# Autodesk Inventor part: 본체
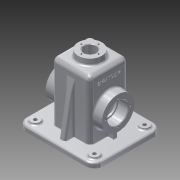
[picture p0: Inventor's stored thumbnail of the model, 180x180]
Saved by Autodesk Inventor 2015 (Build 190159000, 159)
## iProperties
Created: 2016-02
Part Number: 본체
Material: 알루미늄 6061
Document SubType Name: Modeling
Designer: Administrator
Density: 2.7 g/cm^3
Appearance: 알루미늄 - 평지
Mass: 856.212 g
Surface Area: 918.664 cm^2
Volume: 317.116 cm^3
Author: Administrator
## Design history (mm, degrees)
sketch "스케치1"
  geometry: L1 (-65, -57.5)-(65, -57.5); L2 (65, -57.5)-(65, 57.5); L3 (65, 57.5)-(-65, 57.5); L4 (-65, 57.5)-(-65, -57.5); L5 (-65, -57.5)-(65, 57.5); L6 (65, -57.5)-(-65, 57.5); 1 further point
  constraints: 12 end point, 2 midpoint, 2 parallel, 1 horizontal, 1 perpendicular
  dimensions: "d0" = 130 distance of L2.end L3.end; "d1" = 115 distance of L1.end L2.end
extrude "돌출1" new body sketch "스케치1" distance "d2" = 8; taper "d3" = 0 deg
sketch "스케치2"
  geometry: L1 (-60, -52.5)-(60, -52.5); L2 (60, -52.5)-(60, 52.5); L3 (60, 52.5)-(-60, 52.5); L4 (-60, 52.5)-(-60, -52.5); L5 (-60, -52.5)-(60, 52.5); L6 (60, -52.5)-(-60, 52.5); 1 further point
  constraints: 12 end point, 2 midpoint, 2 parallel, 1 horizontal, 1 perpendicular
  dimensions: "d4" = 120 distance of L2.end L3.end; "d5" = 105 distance of L1.end L2.end
extrude "돌출2" join sketch "스케치2" distance "d6" = 2; taper "d7" = 0 deg
sketch "스케치4"
  geometry: L1 (-65, -57.5)-(-65, 57.5) reference; L2 (-65, 57.5)-(65, 57.5) reference; L3 (65, 57.5)-(65, -57.5) reference; L4 (65, -57.5)-(-65, -57.5) reference; L5 (-32.5, -32.5)-(32.5, -32.5); L6 (32.5, -32.5)-(32.5, 32.5); L7 (32.5, 32.5)-(-32.5, 32.5); L8 (-32.5, 32.5)-(-32.5, -32.5); L9 (-32.5, -32.5)-(32.5, 32.5); L10 (32.5, -32.5)-(-32.5, 32.5); L11 (-5, 32.5)-(-5, 47.5); L12 (-5, 47.5)-(5, 47.5); L13 (5, 47.5)-(5, 32.5); L14 (-5, -32.5)-(-5, -47.5); L15 (-5, -47.5)-(5, -47.5); L16 (5, -47.5)-(5, -32.5); L17 (32.5, 3)-(42.5, 3); L18 (42.5, 3)-(42.5, -3); L19 (42.5, -3)-(32.5, -3); L20 (-32.5, 3)-(-42.5, 3); L21 (-42.5, 3)-(-42.5, -3); L22 (-42.5, -3)-(-32.5, -3); 8 further points
  constraints: 36 end point, 9 midpoint, 8 perpendicular, 8 point on line, 4 horizontal, 2 horizontal alignment, 2 parallel, 2 vertical, 2 vertical alignment
  dimensions: "d8" = 65 distance of L6.end L7.end; "d9" = 65 distance of L5.end L6.end; "d10" = 15 distance between parallel lines of L7 L12; "d11" = 10 distance of L11.end L12.end; "d12" = 15 distance between parallel lines of L15 L5; "d13" = 10 distance of L14.end L15.end; "d14" = 10 distance between parallel lines of L6 L18; "d15" = 6 distance of L17.end L18.end; "d16" = 6 distance of L20.end L21.end; "d17" = 10 distance between parallel lines of L21 L8
  node "절단 모서리 투영1"
extrude "돌출3" join sketch "스케치4" distance "d18" = 67.5; taper "d19" = 0 deg
extrude "돌출4" join sketch "스케치4" distance "d20" = 60; taper "d21" = 0 deg
sketch "스케치5"
  geometry: L1 (-75.5, -20)-(-77.5, -20) reference; L2 (-77.5, -20)-(-77.5, 85) reference; L3 (-77.5, 85)-(-75.5, 85) reference; L4 (-75.5, 85)-(-75.5, 90) reference; L5 (-75.5, 90)-(-67.5, 90) reference; L6 (-67.5, 90)-(-67.5, 65) reference; L7 (-67.5, 65)-(-67.5, 35.5) reference; L8 (-67.5, 35.5)-(-7.5, 35.5) reference; L9 (-7.5, 35.5)-(-7.5, 29.5) reference; L10 (-7.5, 29.5)-(-67.5, 29.5) reference; L11 (-67.5, 29.5)-(-67.5, 0) reference; L12 (-67.5, 0)-(-67.5, -25) reference; L13 (-67.5, -25)-(-75.5, -25) reference; L14 (-75.5, -25)-(-75.5, -20) reference; L15 (-67.5, 65)-(0, 65) reference; L16 (0, 65)-(0, 0) reference; L17 (0, 0)-(-67.5, 0) reference; C1 r 27.5 at (-27.5, 32.5); 1 further point
  constraints: 1 centre point, 1 horizontal alignment, 1 tangent
  dimensions: "d22" = 55 diameter of C1
extrude "돌출5" join sketch "스케치5" distance "d23" = 15; taper "d25" = 0 deg; dims "d24" = 80, "d26" = 0
sketch "스케치6"
  geometry: L1 (-32.5, 0)-(-47.5, 0) reference; L2 (-32.5, 0)-(-32.5, 32.5) reference; L3 (-32.5, -32.5)-(-32.5, 0) reference; L4 (32.5, -32.5)-(-32.5, -32.5) reference; L5 (32.5, 0)-(32.5, -32.5) reference; L6 (47.5, 0)-(32.5, 0) reference; L7 (-32.5, 32.5)-(32.5, 32.5) reference; L8 (32.5, 32.5)-(32.5, 0) reference; L9 (-32.5, -32.5)-(32.5, -32.5); L10 (32.5, -32.5)-(32.5, 32.5); L11 (32.5, 32.5)-(-32.5, 32.5); L12 (-32.5, 32.5)-(-32.5, -32.5); L13 (-32.5, -32.5)-(32.5, 32.5); L14 (32.5, -32.5)-(-32.5, 32.5); 1 further point
  constraints: 12 end point, 2 midpoint, 2 parallel, 1 horizontal, 1 perpendicular
extrude "돌출6" join sketch "스케치6" distance "d27" = 32.5; taper "d28" = 0 deg
sketch "스케치7"
  geometry: L1 (-32.5, -32.5)-(-32.5, 32.5) reference; L2 (-32.5, 32.5)-(32.5, 32.5) reference; L3 (32.5, 32.5)-(32.5, -32.5) reference; L4 (32.5, -32.5)-(-32.5, -32.5) reference; C1 r 20 at (0, 0); 1 further point
  constraints: 1 centre point, 1 coincident
  dimensions: "d29" = 40 diameter of C1
extrude "돌출7" join sketch "스케치7" distance "d30" = 10; taper "d31" = 0 deg
extrude "돌출8" join sketch "스케치4" distance "d32" = 110; taper "d33" = 0 deg
feature "면 기울기1" dims angle "d34" = 10 deg
feature "면 기울기2" dims angle "d35" = 10 deg
sketch "스케치10"
  geometry: L1 (-60, -52.5)-(-60, 52.5) reference; L2 (-60, 52.5)-(60, 52.5) reference; L3 (60, 52.5)-(60, -52.5) reference; L4 (60, -52.5)-(-60, -52.5) reference; L5 (27.5, 27.5)-(-27.5, 27.5); L6 (-27.5, 27.5)-(-27.5, -27.5); L7 (-27.5, -27.5)-(27.5, -27.5); L8 (27.5, -27.5)-(27.5, 27.5); L9 (27.5, 27.5)-(-27.5, -27.5); L10 (-27.5, 27.5)-(27.5, -27.5); 1 further point
  constraints: 12 end point, 2 midpoint, 2 parallel, 1 horizontal, 1 perpendicular
  dimensions: "d36" = 55 distance of L6.end L7.end; "d37" = 55 distance of L5.end L6.end
extrude "돌출9" cut sketch "스케치10" distance "d38" = 105; taper "d39" = 0 deg
sketch "스케치11"
  geometry: L1 (-48, -52.5)-(-50, -52.5) reference; L2 (-50, -52.5)-(-50, 52.5) reference; L3 (-50, 52.5)-(-48, 52.5) reference; L4 (-48, 52.5)-(-48, 57.5) reference; L5 (-48, 57.5)-(-40, 57.5) reference; L6 (-40, 57.5)-(-40, -57.5) reference; L7 (-40, -57.5)-(-48, -57.5) reference; L8 (-48, -57.5)-(-48, -52.5) reference; C1 r 27.5 at (0, 0) reference; C2 r 17.5 at (0, 0); 1 further point
  constraints: 1 centre point, 1 coincident
  dimensions: "d40" = 35 diameter of C2
extrude "돌출10" cut sketch "스케치11" distance "d41" = 17; taper "d42" = 0 deg
sketch "스케치12"
  geometry: L1 (50, -52.5)-(48, -52.5) reference; L2 (48, -52.5)-(48, -57.5) reference; L3 (48, -57.5)-(40, -57.5) reference; L4 (40, -57.5)-(40, 57.5) reference; L5 (40, 57.5)-(48, 57.5) reference; L6 (48, 57.5)-(48, 52.5) reference; L7 (48, 52.5)-(50, 52.5) reference; L8 (50, 52.5)-(50, -52.5) reference; C1 r 27.5 at (0, 0) reference; C2 r 17.5 at (0, 0); 1 further point
  constraints: 1 centre point, 1 coincident
  dimensions: "d43" = 35 diameter of C2
extrude "돌출11" cut sketch "스케치12" distance "d44" = 17; taper "d45" = 0 deg
sketch "스케치13"
  geometry: L1 (50, -52.5)-(48, -52.5) reference; L2 (48, -52.5)-(48, -57.5) reference; L3 (48, -57.5)-(40, -57.5) reference; L4 (40, -57.5)-(40, -32.5) reference; L5 (40, -32.5)-(-60, -32.5) reference; L6 (-60, -32.5)-(-60, 32.5) reference; L7 (-60, 32.5)-(40, 32.5) reference; L8 (40, 32.5)-(40, 57.5) reference; L9 (40, 57.5)-(48, 57.5) reference; L10 (48, 57.5)-(48, 52.5) reference; L11 (48, 52.5)-(50, 52.5) reference; L12 (50, 52.5)-(50, -52.5) reference; C1 r 17.5 at (0, 0) reference; C2 r 15 at (0, 0); 1 further point
  constraints: 1 centre point, 1 coincident
  dimensions: "d46" = 30 diameter of C2
extrude "돌출12" cut sketch "스케치13" stored distance "d47" = 17; taper "d48" = 0 deg
sketch "스케치14"
  geometry: C1 r 20 at (0, 0) reference; C2 r 10.5 at (0, 0); 1 further point
  constraints: 1 centre point, 1 coincident
  dimensions: "d49" = 21 diameter of C2
extrude "돌출13" cut sketch "스케치14" stored distance "d50" = 17; taper "d51" = 0 deg
sketch "스케치15"
  geometry: C1 r 10.5 at (0, 0) reference; C2 r 20 at (0, 0) reference; 5 further points
  constraints: 1 vertical alignment, 5 other
  dimensions: "d52" = 14.5 distance of point (0, 0) point (0, 14.5); "d55" = 360 deg dimension on point (0, 0) point (0, 14.5) (derived)
hole "구멍1" sketch "스케치15" at (0, 14.5), (-14.5, 0), (0, -14.5), (14.5, 0) diameter "d57" = 2.459; stored, may be unused: countersink angle "d61" = 90 deg, drill point angle "d63" = 118 deg; dims "d58" = 7, "d59" = 4, "d60" = 2, "d62" = 9
sketch "스케치16"
  geometry: L1 (-48, -52.5)-(-50, -52.5) reference; L2 (-50, -52.5)-(-50, 52.5) reference; L3 (-50, 52.5)-(-48, 52.5) reference; L4 (-48, 52.5)-(-48, 57.5) reference; L5 (-48, 57.5)-(-40, 57.5) reference; L6 (-40, 57.5)-(-40, -57.5) reference; L7 (-40, -57.5)-(-48, -57.5) reference; L8 (-48, -57.5)-(-48, -52.5) reference; C1 r 17.5 at (0, 0) reference; C2 r 27.5 at (0, 0) reference; 5 further points
  constraints: 1 horizontal alignment, 5 other
  dimensions: "d64" = 21 distance of C1.centre point (21, 0); "d67" = 360 deg dimension on C1.centre point (21, 0) (derived)
hole "구멍2" sketch "스케치16" at (21, 0), (0, 21), (-21, 0), (0, -21) diameter "d69" = 3.242; stored, may be unused: countersink angle "d73" = 90 deg, drill point angle "d75" = 118 deg; dims "d70" = 8, "d71" = 4, "d72" = 2, "d74" = 10
sketch "스케치17"
  geometry: L1 (50, -52.5)-(48, -52.5) reference; L2 (48, -52.5)-(48, -57.5) reference; L3 (48, -57.5)-(40, -57.5) reference; L4 (40, -57.5)-(40, 57.5) reference; L5 (40, 57.5)-(48, 57.5) reference; L6 (48, 57.5)-(48, 52.5) reference; L7 (48, 52.5)-(50, 52.5) reference; L8 (50, 52.5)-(50, -52.5) reference; C1 r 17.5 at (0, 0) reference; C2 r 27.5 at (0, 0) reference; 5 further points
  constraints: 1 horizontal alignment, 5 other
  dimensions: "d76" = 21 distance of C1.centre point (-21, 0); "d79" = 360 deg dimension on C1.centre point (-21, 0) (derived)
hole "구멍3" sketch "스케치17" at (-21, 0), (0, -21), (21, 0), (0, 21) diameter "d81" = 3.242; stored, may be unused: countersink angle "d85" = 90 deg, drill point angle "d87" = 118 deg; dims "d82" = 8, "d83" = 4, "d84" = 2, "d86" = 10
fillet "모깎기1" dims "d88" = 15
sketch "스케치18"
  geometry: L1 (-50, 57.5)-(50, 57.5) reference; L2 (65, 42.5)-(65, -42.5) reference; L3 (50, -57.5)-(-50, -57.5) reference; L4 (-65, -42.5)-(-65, 42.5) reference; L5 (27.5, -27.5)-(27.5, 27.5) reference; L6 (27.5, 27.5)-(-27.5, 27.5) reference; L7 (-27.5, 27.5)-(-27.5, -27.5) reference; L8 (-27.5, -27.5)-(27.5, -27.5) reference; L9 (-32.5, 3)-(-32.5, 32.5) reference; L10 (-32.5, 32.5)-(-5, 32.5) reference; L11 (-5, 32.5)-(-5, 47.5) reference; L12 (-5, 47.5)-(5, 47.5) reference; L13 (5, 47.5)-(5, 32.5) reference; L14 (5, 32.5)-(32.5, 32.5) reference; L15 (32.5, 32.5)-(32.5, 3) reference; L16 (32.5, 3)-(42.5, 3) reference; L17 (42.5, 3)-(42.5, -3) reference; L18 (42.5, -3)-(32.5, -3) reference; L19 (32.5, -3)-(32.5, -32.5) reference; L20 (32.5, -32.5)-(5, -32.5) reference; L21 (5, -32.5)-(5, -47.5) reference; L22 (5, -47.5)-(-5, -47.5) reference; L23 (-5, -47.5)-(-5, -32.5) reference; L24 (-5, -32.5)-(-32.5, -32.5) reference; L25 (-32.5, -32.5)-(-32.5, -3) reference; L26 (-32.5, -3)-(-42.5, -3) reference; L27 (-42.5, -3)-(-42.5, 3) reference; L28 (-42.5, 3)-(-32.5, 3) reference; C1 r 7.5 at (-50, 42.5); C2 r 7.5 at (50, 42.5); C3 r 7.5 at (50, -42.5); C4 r 7.5 at (-50, -42.5); A1 r 15 centre (-50, 42.5) between (-50, 57.5) and (-65, 42.5) reference; A2 r 15 centre (50, 42.5) between (65, 42.5) and (50, 57.5) reference; A3 r 15 centre (50, -42.5) between (50, -57.5) and (65, -42.5) reference; A4 r 15 centre (-50, -42.5) between (-65, -42.5) and (-50, -57.5) reference; 1 further point
  constraints: 4 centre point, 4 coincident
  dimensions: "d89" = 15 diameter of C1; "d90" = 15 diameter of C2; "d91" = 15 diameter of C3; "d92" = 15 diameter of C4
extrude "돌출14" join sketch "스케치18" distance "d93" = 3; taper "d94" = 0 deg
sketch "스케치19"
  geometry: L1 (-22.5, 15)-(-22.5, 70) reference; L2 (-22.5, 70)-(-77.5, 70) reference; L3 (-77.5, 70)-(-77.5, 15) reference; L4 (-77.5, 15)-(-22.5, 15) reference; L5 (-82.5, 45.5)-(-82.5, 75) reference; L6 (-82.5, 75)-(-55, 75) reference; L7 (-55, 75)-(-55, 89.471) reference; L8 (-55, 89.471)-(-45, 89.471) reference; L9 (-45, 89.471)-(-45, 75) reference; L10 (-45, 75)-(-17.5, 75) reference; L11 (-17.5, 75)-(-17.5, 45.5) reference; L12 (-17.5, 45.5)-(-7.5, 45.5) reference; L13 (-7.5, 45.5)-(-7.5, 39.5) reference; L14 (-7.5, 39.5)-(-17.5, 39.5) reference; L15 (-17.5, 39.5)-(-17.5, 10) reference; L16 (-17.5, 10)-(-45, 10) reference; L17 (-45, 10)-(-45, -4.471) reference; L18 (-45, -4.471)-(-55, -4.471) reference; L19 (-55, -4.471)-(-55, 10) reference; L20 (-55, 10)-(-82.5, 10) reference; L21 (-82.5, 10)-(-82.5, 39.5) reference; L22 (-82.5, 39.5)-(-92.5, 39.5) reference; L23 (-92.5, 39.5)-(-92.5, 45.5) reference; L24 (-92.5, 45.5)-(-82.5, 45.5) reference; C1 r 7.5 at (0, 0) reference; C2 r 7.5 at (-100, 85) reference; C3 r 7.5 at (0, 85) reference; C4 r 7.5 at (-100, 0) reference; C5 r 3 at (-100, 85); C6 r 3 at (0, 85); C7 r 3 at (0, 0); C8 r 3 at (-100, 0); 1 further point
  constraints: 4 centre point, 4 coincident
  dimensions: "d95" = 6 diameter of C5; "d96" = 6 diameter of C6; "d97" = 6 diameter of C7; "d98" = 6 diameter of C8
extrude "돌출15" cut sketch "스케치19" stored distance "d99" = 3; taper "d100" = 0 deg
chamfer "모따기1" distance "d101" = 1; stored, may be unused: second distance "d102" = 2, angle "d103" = 45 deg
fillet "모깎기2" dims "d104" = 0.3
fillet "모깎기4" dims "d106" = 8
fillet "모깎기6" dims "d108" = 10
fillet "모깎기7" dims "d109" = 3
fillet "모깎기8" dims "d110" = 3
fillet "모깎기9" dims "d111" = 3
feature "면 기울기3" dims angle "d112" = 5 deg
fillet "모깎기10" dims "d113" = 3
node "작업 평면1"
sketch "스케치21"
  geometry: L1 (-18, 44.5)-(-18, 4.5) reference; L2 (0, -8)-(92, -8) reference; 2 further points
  constraints: 1 other
  dimensions: "d117" = 26 distance from line of point (8, 24.5) L1; "d118" = 32.5 distance from line of L2 point (8, 24.5)
feature "엠보싱1" sketch "스케치21" dims "d8" = 65, "d9" = 65, "d10" = 15, "d11" = 10, "d12" = 15, "d13" = 10, "d14" = 10, "d15" = 6, "d16" = 6, "d17" = 10, "d119" = 0.5, "d120" = 0
fillet "모깎기11" dims "d121" = 1
fillet "모깎기12" dims "d122" = 3
fillet "모깎기13" dims "d123" = 3
node "솔리드1"
node "절단 모서리 투영2"
node "절단 모서리 투영3"
node "절단 모서리 투영4"
node "절단 모서리 투영5"
node "절단 모서리 투영6"
node "절단 모서리 투영7"
node "절단 모서리 투영8"
node "절단 모서리 투영9"
node "절단 모서리 투영10"
node "절단 모서리 투영11"
node "절단 모서리 투영12"
node "절단 모서리 투영13"
node "절단 모서리 투영14"
other parameters: "d116" = 24.25
